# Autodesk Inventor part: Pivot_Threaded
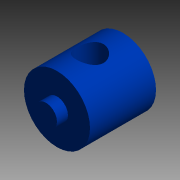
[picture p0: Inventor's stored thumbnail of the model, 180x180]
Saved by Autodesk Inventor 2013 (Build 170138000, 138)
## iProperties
Shininess: 0.0
Length Units: 11272
Angle Units: 11279
Time Units: 11290
Mass Units: 11283
Length Display Precision: 2
Angle Display Precision: 1
Compacted: True
Created: 1999-05
Part Number: Pivot_Threaded
Document SubType Name: Modeling
Designer: Administrator
Density: 7.85 g/cm^3
Material: Steel
Mass: 37.2426 g
Surface Area: 21.7773 cm^2
Volume: 4.74428 cm^3
Density: 0.0
Volumn: 0.0
Area: 0.0
PropertySet Name: Model Information
Control State: 0
Master: False
Checked Out: False
Author: Administrator
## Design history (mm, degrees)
node "y-z Plane"
  node "x-z Plane"
  node "x-y Plane"
node "Extrusion1" dims "d1" = 19.05, "d2" = 0
  sketch "Sketch1"
    geometry: C1 r 9.525 at (0, 0); 1 further point
    constraints: 1 centre point, 1 coincident
    dimensions: "d0" = 19.05 diameter of C1
node "Extrusion2" dims "d3" = 3.175, "d4" = 0
  sketch "Sketch2"
    geometry: C1 r 9.525 at (0, 0) reference; C2 r 3.175 at (0, 0)
    constraints: 1 centre point
    dimensions: "d18" = 6.35 diameter of C2
node "Extrusion3" dims "d6" = 3.175, "d7" = 0
  sketch "Sketch3"
    geometry: C1 r 9.525 at (0, 0) reference; C2 r 3.175 at (0, 0)
    constraints: 1 centre point
    dimensions: "d5" = 6.35 diameter of C2
workplane "Work Plane1"
  workaxis "Work Axis1"
workplane "Work Plane2"
node "Hole1" dims "d12" = 7.7978, "d13" = 9.525, "d14" = 6.35, "d15" = 60 deg, "d16" = 19.05, "d17" = 118 deg
  sketch "Sketch4"
    geometry: 2 further points
    constraints: 1 coincident
node "Sketch5"
node "Sketch6"
workaxis "Work Axis2"
body "Solid1"
other parameters: "d8" = 0, "d9" = 9.525
